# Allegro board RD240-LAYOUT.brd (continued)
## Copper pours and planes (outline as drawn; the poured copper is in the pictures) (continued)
CS on BOTTOM: 256.9,5.21 256.89,5.28 256.9,5.35 256.95,5.4 256.91,5.43 256.89,5.47 256.89,5.52 256.95,5.64 257.08,5.66 257.46,5.55 257.62,5.55 257.78,5.58 257.95,5.75 257.95,6.47 257.81,6.61 257.62,6.65 256.3,6.65 256.24,6.66 256.19,6.69 254.96,7.93 254.92,7.98 254.91,8.04 254.91,8.24 254.78,8.61 254.77,8.66 254.76,8.71 254.76,8.82 255.06,9.12 255.36,8.82 255.36,8.71 255.36,8.66 255.34,8.61 255.21,8.24 255.21,8.1 256.36,6.95 257.62,6.95 257.95,7.02 258,7.03 258.18,7.03 258.33,6.96 258.4,6.8 258.4,5.4 258.33,5.24 258.18,5.17 258,5.17 257.95,5.18 257.62,5.25 257.46,5.25 257.08,5.14 257.01,5.13 256.95,5.16
CS on BOTTOM: 262.17,6.39 261.79,6.5 261.43,6.5 261.37,6.51 261.32,6.54 261.21,6.65 261.2,6.65 259.58,6.65 259.25,6.58 259.2,6.58 259.02,6.58 258.8,6.8 259.02,7.03 260.65,7.03 260.97,7.09 261.02,7.1 261.2,7.1 261.36,7.03 261.42,6.86 261.49,6.8 261.79,6.8 262.17,6.91 262.23,6.92 262.28,6.9 262.35,6.83 262.36,6.73 262.34,6.69 262.3,6.65 262.32,6.64 262.34,6.61 262.36,6.58 262.34,6.44 262.21,6.38
CS on BOTTOM: 243.29,13.6 239.59,13.6 239.49,13.62 239.41,13.67 235.3,17.78 233.7,17.78 233.61,17.8 233.53,17.86 223.77,27.62 223.59,27.62 223.56,27.6 223.04,27.45 222.97,27.45 222.7,27.45 222.52,27.45 222.35,27.51 222.16,27.74 222.14,28.03 222.14,28.15 222.14,28.22 222.16,28.28 222.35,28.92 222.35,29.51 222.33,29.53 222.31,29.54 222.24,29.61 222.21,29.65 222.2,29.71 222.2,29.8 222.24,29.91 222.35,29.95 222.36,29.95 222.6,30.13 222.84,29.95 222.85,29.95 222.96,29.91 223,29.8 223,29.71 222.99,29.65 222.96,29.61 222.89,29.54 222.87,29.53 222.85,29.51 222.85,28.92 223.02,28.37 223.06,28.36 223.1,28.35 223.75,28.16 223.83,28.16 223.92,28.14 224,28.09 233.81,18.28 235.41,18.28 235.5,18.26 235.58,18.21 239.69,14.1 243.39,14.1 243.49,14.08 243.57,14.03 244.16,13.44 244.16,13.08 243.81,13.08
CSA on TOP (solid shape): 107.08,84.48 107.12,84.62 107.24,84.67 108.5,84.54 108.6,84.5 108.64,84.4 108.59,84.29 108.49,84.25 108.47,84.25 108.24,84.27 107.61,83.56 107.67,83.33 107.56,83.14 107.38,83.26
CSA on TOP: 130.48,48.24 130.31,48.3 130.33,48.49 130.35,48.5 130.33,48.51 130.31,48.7 130.48,48.76 130.84,48.65 134.76,48.65 135.45,49.34 135.36,49.63 135.35,49.67 135.35,49.71 135.35,49.9 135.43,50.09 135.62,50.17 136.22,50.17 136.26,50.17 136.31,50.16 136.66,50.05 137.18,50.05 137.24,50.04 137.29,50.01 137.53,49.76 137.8,49.82 137.88,49.83 138.1,49.6 137.88,49.38 137.8,49.38 137.41,49.47 137.38,49.49 137.12,49.75 136.66,49.75 136.31,49.64 136.26,49.63 136.22,49.62 135.89,49.62 135.77,49.26 135.75,49.22 135.73,49.19 134.93,48.39 134.89,48.37 134.86,48.35 134.82,48.35 130.84,48.35
CSA on BOTTOM: 157.43,1.52 157.2,1.75 157.43,1.98 157.55,1.98 157.6,1.97 157.93,1.9 158.74,1.9 159.05,2.21 159.05,2.86 158.94,3.22 159,3.39 159.19,3.37 159.2,3.35 159.21,3.37 159.4,3.39 159.46,3.22 159.35,2.86 159.35,2.15 159.34,2.09 158.91,1.64 158.87,1.62 158.83,1.6 158.8,1.6 157.93,1.6 157.6,1.53 157.55,1.52
CSA on BOTTOM: 156.4,1.52 156.35,1.53 156.02,1.6 154.93,1.6 154.87,1.61 154.82,1.64 154.58,1.88 154.23,2.14 154.2,2.25 154.2,2.41 154.21,2.46 154.26,2.7 152.86,4.1 152.3,4.1 152.26,4.11 152.22,4.13 152.2,4.14 151.89,4.42 151.24,5.08 150.43,5.08 150.22,5.28 150.43,5.47 150.96,5.47 151.28,5.42 151.32,5.41 151.36,5.38 152.1,4.64 152.36,4.4 152.93,4.4 152.98,4.39 153.03,4.36 154.53,2.86 154.56,2.82 154.57,2.78 154.64,2.46 154.65,2.41 154.65,2.32 154.8,2.09 154.99,1.9 156.02,1.9 156.35,1.97 156.4,1.98 156.57,1.98 156.8,1.75 156.57,1.52
CSB on TOP: 123.9,82.45 122.85,83.5 123.9,84.55 124.7,84.55 124.99,84.51 125.26,84.39 126.01,83.91 126.56,83.91 126.67,83.86 126.71,83.75 126.72,83.73 126.75,83.64 126.71,83.55 126.71,83.53 126.67,83.42 126.56,83.38 126.54,83.38 126.5,83.36 126.45,83.35 126.42,83.35 124.99,82.49 124.7,82.45
CSB on TOP: 152.16,44.85 152.1,44.85 152.04,44.86 151.99,44.89 151.77,45.12 151.74,45.17 151.72,45.23 151.72,45.56 151.67,45.73 151.43,45.73 151.39,45.73 151.35,45.74 150.96,45.85 150.82,45.85 150.77,45.86 150.72,45.89 150.59,46.02 150.45,46.02 150.13,45.96 150.08,45.95 149.9,45.95 149.68,46.17 149.9,46.4 150.08,46.4 150.13,46.39 150.45,46.33 150.65,46.33 150.71,46.31 150.89,46.15 150.96,46.15 151.35,46.26 151.39,46.27 151.43,46.27 151.88,46.27 152.1,46.16 152.14,45.92 152.03,45.56 152.03,45.29 152.16,45.15 152.16,45.15 152.52,45.26 152.69,45.2 152.67,45.01 152.65,45 152.67,44.99 152.69,44.8 152.52,44.74
CSB on BOTTOM: 156.4,2.92 156.35,2.93 156.02,3 154.9,3 154.84,3.01 154.79,3.04 153.51,4.33 153.48,4.36 153.4,4.74 153.06,4.81 152.43,4.82 152.38,4.85 151.51,5.72 150.43,5.72 150.22,5.92 150.43,6.12 151.12,6.12 151.15,6.12 151.43,6.08 151.53,6.08 151.58,6.06 152.55,5.11 153.06,5.11 153.39,5.18 153.44,5.18 153.62,5.18 153.77,5.12 153.84,4.96 153.84,4.79 153.83,4.75 153.78,4.48 154.96,3.3 156.02,3.3 156.35,3.37 156.4,3.38 156.57,3.38 156.8,3.15 156.57,2.92
CSB on BOTTOM: 126.41,83.46 126.36,83.52 126.19,83.85 126.09,83.94 126.06,83.99 126.05,84.05 126.05,85.3 126.06,85.36 126.49,85.81 126.53,85.83 127.06,86.1 127.26,86.04 127.21,85.84 127.2,85.83 126.97,85.72 126.97,85.68 127.2,85.57 127.21,85.56 127.26,85.36 127.06,85.3 126.72,85.47 126.58,85.47 126.35,85.24 126.35,84.11 126.4,84.06 126.73,83.89 126.76,83.87 126.78,83.84 126.8,83.71 126.69,83.62 126.67,83.61 126.64,83.61 126.64,83.58 126.63,83.55 126.58,83.47 126.49,83.44
FG1 on BOTTOM: 27.31,41.8 27.25,41.81 27.21,41.84 23.94,45.1 23.91,45.15 23.9,45.21 23.9,48.19 23.9,48.21 23.92,48.22 24.73,49.02 25.39,49.95 25.4,49.96 33.94,58.51 33.99,58.54 34.05,58.55 40.49,58.55 40.55,58.54 40.59,58.51 42.86,56.24 42.89,56.2 42.9,56.14 42.9,52.03 42.89,51.98 42.86,51.93 32.77,41.84 32.72,41.81 32.66,41.8
FG2 on BOTTOM: 6.11,0.62 5.82,0.68 5.58,0.84 4.72,1.7 4.56,1.94 4.5,2.23 4.5,6.75 4.72,7.28 5.25,7.5 9.35,7.5 9.64,7.44 9.88,7.28 10.62,6.54 13.8,4.75 20.83,4.75 21.31,5.23 22.37,5.23 22.37,4.17 21.68,3.47 21.43,3.31 21.14,3.25 13.8,3.25 11.12,1.74 10.22,0.84 9.98,0.68 9.69,0.62
FG3 on BOTTOM: 68.04,52.19 67.2,52.19 67.14,52.13 67.07,52.07 65.01,50.63 64.99,50.62 63.96,50.82 64.15,51.86 65.75,52.98 65.75,54.02 64.15,55.14 64.01,55.26 63.91,55.42 63.72,55.4 63.54,55.43 61.6,55.97 60.53,54.9 61.07,52.96 60.57,52.04 59.64,52.52 59.63,52.56 58.37,57.07 57.6,57.92 57.54,58.21 57.54,58.55 58.29,59.3 59.04,58.55 59.04,58.52 59.43,58.13 63.94,56.87 63.98,56.86 64.23,56.72 64.41,56.49 64.71,56.49 64.99,56.38 65.01,56.37 68.23,54.11 68.28,54.07 68.33,54.03 71.63,50.73 71.63,49.67 70.57,49.67
FG4 on BOTTOM (solid shape): 78.41,10.05 79.3,10.6 80.19,10.05 82.43,5.56 82.39,4.59 81.54,4.12 81.01,4.27 80.64,4.67 80.36,5.24 78.24,5.24 77.96,4.67 76.62,4.22 76.17,5.56
FG4 on BOTTOM: 75.95,0.5 75.84,0.54 75.8,0.65 75.8,3.85 75.84,3.96 75.95,4 76.65,4 76.76,3.96 76.8,3.86 77.36,2.42 78.65,1.59 78.92,1.89 79.31,2 80.81,2.01 81.07,2.23 81.29,2.49 81.29,2.73 81.29,2.73 81.25,2.97 81.29,3.21 81.29,3.22 81.3,3.99 82.05,4.73 82.8,3.98 82.8,3.87 82.8,3.85 82.8,3.23 84.01,2.02 110.05,2.02 111.99,3.96 113.05,3.96 113.05,2.9 110.89,0.74 110.65,0.58 110.36,0.52 83.07,0.52 83.04,0.51 83,0.5
FG6 on BOTTOM: 295,12.65 295.04,12.76 295.15,12.8 295.59,12.8 295.65,12.79 295.69,12.76 296.15,12.3 299,12.3 299.4,12.7 299.4,16.45 299.4,16.48 299.41,16.5 299.4,16.52 299.4,16.55 299.4,18.65 299.41,18.7 299.44,18.75 304.39,23.7 304.51,23.88 304.55,24.09 304.55,39.76 304.53,39.91 304.46,40.08 304.45,40.12 304.45,43.35 304.49,43.46 304.6,43.5 305.7,43.5 305.91,43.41 306,43.2 306,16.55 306,16.52 305.99,16.5 306,16.48 306,16.45 306,2 305.56,0.94 304.5,0.5 295.87,0.5 295.76,0.52 295.66,0.59 295.09,1.16 295.02,1.26 295,1.37 295,4.5 ; 2 cut-outs
FG7 on BOTTOM: 296.2,127.58 296.24,127.68 296.35,127.72 297,127.72 297.15,127.88 297.2,127.91 297.26,127.92 298.52,127.92 298.67,127.96 298.73,128.01 298.87,128.15 298.95,128.29 298.96,128.36 298.96,130.42 298.97,130.48 299,130.52 300.89,132.41 300.95,132.46 301.1,132.5 302.48,132.5 302.52,132.5 304.5,132.5 305.09,132.38 305.56,132.06 305.89,131.56 306,131 306,127.88 305.99,127.81 305.91,127.67 305.58,127.34 302.73,125.51 299.66,126.96 296.35,126.96 296.24,127 296.2,127.11 ; 1 cut-out
GDA on TOP: 148.44,42.72 148.46,42.75 148.52,42.87 144.04,47.35 142.1,47.35 142.04,47.36 141.99,47.39 141.67,47.72 141.64,47.77 141.62,47.83 141.62,47.87 141.56,48.17 141.55,48.23 141.55,48.56 141.56,48.61 141.64,48.97 141.79,49.13 141.79,50.14 142.06,50.42 142.34,50.14 142.34,49.52 142.33,49.46 142.14,49.07 142.13,49.04 142.11,49.02 142,48.91 142,48.58 142,48.56 142,48.23 141.99,48.17 141.93,47.88 142.16,47.65 144.1,47.65 144.16,47.64 148.81,43.01 148.83,42.97 148.94,42.75 148.96,42.72 148.96,42.68 148.9,42.56 148.76,42.54 148.73,42.56 148.7,42.58 148.67,42.56 148.64,42.54 148.5,42.56 148.44,42.68
GDB on TOP (solid shape): 139.58,2.27 139.54,2.47 139.75,2.51 140.81,1.77 140.87,1.65 140.81,1.53 139.75,0.79 139.59,0.78 139.51,0.91 139.53,0.98 139.58,1.03 139.78,1.17 139.78,2.13
GDB on TOP: 149.76,42.33 149.58,42.31 149.51,42.49 149.6,42.69 144.69,47.62 144.68,47.67 144.68,47.87 144.61,48.17 144.6,48.23 144.6,48.98 144.53,49.1 144.4,49.3 144.35,49.41 144.33,49.53 144.33,50.14 144.74,50.55 145.16,50.14 145.16,49.53 145.15,49.46 145.14,49.4 144.98,48.91 145.04,48.63 145.05,48.58 145.05,48.23 145.04,48.17 144.97,47.87 144.97,47.74 149.88,42.83 149.91,42.78 150.03,42.49 149.97,42.31 149.78,42.33 149.77,42.34
HS1_1 on TOP: 175.2,122.9 175.14,122.91 175.09,122.93 175.05,122.95 175.02,122.97 173.43,124.57 171.34,126.32 171.3,126.37 171.28,126.42 171.36,126.72 171.67,126.71 172.75,125.79 174.45,125.79 175.53,126.71 175.57,126.73 175.62,126.75 175.88,126.68 175.93,126.42 175.9,126.37 175.85,126.32 174.18,124.91 174.13,124.86 174.13,124.58 175.3,123.4 176.57,123.4 176.82,123.15 176.57,122.9
HS1_2 on TOP (solid shape): 88.47,131.85 88.73,131.87 88.86,131.65 88.84,131.53 88.76,131.44 87.94,130.86 87.94,127.14 88.76,126.56 88.82,126.21 88.47,126.15 84.75,128.8 84.65,129 84.75,129.2 87.54,131.19
LGND on TOP (solid shape): 221.06,23.49 221.23,23.21 221.53,22 221.32,21.47 220.75,21.48 220.18,21.47 219.97,22 220.26,23.21 220.44,23.49 220.75,23.6
LGND on TOP: outline of 128 points within 226.85,55.94 242.53,90.55 ; 2 cut-outs
LGND on TOP: 231.3,16.58 230.94,16.94 231.3,17.3 231.32,17.3 231.39,17.29 231.46,17.28 231.73,17.17 232.02,17.17 232.4,17.28 232.44,17.29 232.48,17.29 233.69,17.29 233.73,17.29 234.15,17.17 234.74,17.17 235.13,17.28 235.17,17.29 235.22,17.28 235.29,17.23 235.32,17.14 235.32,17.12 235.34,17.07 235.35,17.02 235.34,16.97 235.32,16.92 235.32,16.9 235.26,16.78 235.13,16.75 234.74,16.87 234.15,16.87 233.73,16.75 233.69,16.74 232.48,16.74 232.44,16.75 232.4,16.75 232.28,16.79 231.93,16.79 231.46,16.6 231.39,16.59 231.32,16.58
LGND on TOP: outline of 210 points within 232.9,48 306,132.5
LGND on TOP: 214.52,15.45 214.43,15.88 214.45,15.94 214.48,16 214.45,16.06 214.43,16.12 214.52,16.55 214.92,16.74 214.98,16.74 215.04,16.72 215.7,16.55 219.44,20.3 219.44,20.52 219.27,20.69 219.16,20.86 219.12,21.05 219.12,21.26 219.16,21.45 219.27,21.61 219.45,21.8 219.62,21.91 219.81,21.95 220.62,21.95 221.05,21.86 221.25,21.46 221.25,20.9 221.21,20.71 221.1,20.55 216.2,15.65 216.1,15.57 215.97,15.52 215.04,15.27 214.98,15.26 214.92,15.26
LGND on BOTTOM: outline of 92 points within 225.45,76 242.45,93.3
LGND on BOTTOM: outline of 129 points within 232.9,48.23 305,132.5 ; 6 cut-outs
LGND on BOTTOM: 234.86,109.05 234.8,109.06 234.76,109.09 234.05,109.8 233.05,109.8 232.94,109.84 232.9,109.95 232.9,112.99 232.97,113.12 233.11,113.13 233.15,113.11 233.96,113.34 233.67,114.13 233.65,114.14 233.4,114.22 233.14,114.19 232.96,114.24 232.98,114.43 233.61,115.06 233.65,115.09 233.71,115.1 235.02,115.1 235.05,115.17 235.05,115.42 235.07,115.52 235.12,115.6 235.5,115.98 235.85,115.98 235.85,115.62 235.55,115.32 235.55,115.17 235.58,115.1 237.4,115.1 239.06,116.76 239.1,116.79 239.16,116.8 240.45,116.8 240.56,116.76 240.6,116.65 240.6,109.2 240.56,109.09 240.45,109.05
LGND on BOTTOM: 289.82,42.61 289.9,42.6 292.76,42.6 292.94,42.63 293.08,42.73 293.86,43.51 293.9,43.54 293.96,43.55 300.3,43.55 300.42,43.53 302.68,41.3 304.11,39.87 304.14,39.82 304.15,39.76 304.15,24.09 304.14,24.03 304.11,23.98 298.99,18.86 298.91,18.73 298.9,18.65 298.9,13.94 298.89,13.88 298.86,13.83 298.78,13.75 298.62,13.48 298.6,13.33 298.6,12.9 298.56,12.79 298.45,12.75 296.26,12.75 296.2,12.76 296.16,12.79 295.84,13.11 295.7,13.19 295.63,13.2 282.72,13.2 282.65,13.21 282.51,13.29 280.95,14.85 274.58,14.85 274.52,14.86 274.48,14.89 273.84,15.53 273.81,15.57 273.8,15.63 273.8,43.25 273.84,43.4 273.95,43.51 274.1,43.55 288.9,43.55 289.05,43.51 289.16,43.4 289.2,43.25 289.2,43.07 289.24,42.92 289.29,42.86 289.37,42.78 289.38,42.77 289.51,42.66 289.67,42.62 ; 3 cut-outs
LGND on BOTTOM: 234.48,55.97 234.39,56 234.33,56.08 234.26,56.22 234.08,56.35 234.05,56.4 234.02,56.43 233.1,56.43 232.99,56.47 232.95,56.58 232.95,60 232.96,60.06 232.99,60.1 233.15,60.26 233.19,60.29 233.25,60.3 235.93,60.3 235.96,60.3 236,60.28 236.65,60.39 236.77,61.05 236.76,61.14 236.8,61.22 236.87,61.34 236.9,61.48 236.9,62.12 236.79,62.39 236.53,62.5 234.36,62.5 234.3,62.51 234.26,62.54 234.25,62.55 234.21,62.6 234.2,62.66 234.07,62.79 233.1,62.79 232.99,62.83 232.95,62.94 232.95,65.73 232.99,65.84 233.1,65.88 233.31,65.88 233.49,66.06 233.49,66.38 233.5,66.42 233.52,66.67 233.43,66.91 233.41,67.01 233.45,67.1 235.91,69.56 235.97,69.61 236.12,69.65 239.16,69.65 239.2,69.64 239.35,69.57 239.47,69.55 240.24,69.55 240.35,69.57 240.5,69.64 240.54,69.65 241.3,69.65 241.45,69.61 241.56,69.5 241.6,69.35 241.6,58.75 241.59,58.69 241.56,58.65 238.92,56.01 238.88,55.98 238.82,55.97
LGND on BOTTOM: 222.19,24.75 222.13,24.76 222.06,24.77 221.42,24.96 220.27,24.96 220.17,24.98 220.09,25.03 219.87,25.25 219.87,25.61 220.22,25.61 220.37,25.46 221.42,25.46 222.06,25.65 222.13,25.67 222.19,25.67 222.58,25.67 223.04,25.21 222.58,24.75
LGND on BOTTOM: 239.26,119.28 239.2,119.29 239.16,119.32 238.92,119.56 238.89,119.6 238.88,119.66 238.88,121.3 238.71,121.71 238.3,121.88 235.17,121.88 235.06,121.92 235.02,122.03 235.02,123.15 235.06,123.26 235.17,123.3 239.85,123.3 239.91,123.29 239.95,123.26 240.16,123.05 240.19,123.01 240.2,122.95 240.2,119.46 240.19,119.4 240.16,119.36 240.12,119.32 240.07,119.29 240.01,119.28
LGND on CONDUCTIVE2: outline of 167 points within 194.56,1.55 304.95,131.45 ; 167 cut-outs
LGND on CONDUCTIVE5: outline of 187 points within 194.56,1.55 304.95,131.45 ; 166 cut-outs
OUTA1 on TOP: 140.68,115.44 140.51,115.5 140.53,115.69 140.55,115.7 140.53,115.71 140.51,115.9 140.68,115.96 141.04,115.85 142.15,115.85 142.47,116.18 142.47,116.42 142.41,116.75 142.4,116.8 142.4,116.94 142.41,116.98 142.49,117.37 142.67,117.55 142.67,117.65 142.5,118.07 142.54,118.4 142.84,118.56 143.06,118.56 143.13,118.55 143.2,118.53 143.63,118.35 144.29,118.35 144.59,118.65 144.63,118.68 144.67,118.69 144.7,118.7 145.07,118.7 145.54,118.92 145.63,118.95 145.72,118.96 146.45,118.96 146.86,118.55 146.45,118.14 145.72,118.14 145.63,118.15 145.54,118.17 145.07,118.4 144.76,118.4 144.46,118.09 144.42,118.07 144.39,118.05 144.35,118.05 143.63,118.05 143.14,117.85 143.09,117.84 142.99,117.6 142.99,117.51 142.98,117.45 142.8,117.26 142.8,117.2 142.84,116.98 142.85,116.94 142.85,116.8 142.84,116.75 142.78,116.42 142.78,116.11 142.76,116.06 142.32,115.59 142.28,115.57 142.24,115.55 142.21,115.55 141.04,115.55
OUTB1 on TOP: 140.68,112.04 140.51,112.1 140.53,112.29 140.55,112.3 140.53,112.31 140.51,112.5 140.68,112.56 141.04,112.45 142.16,112.45 142.47,112.77 142.47,113.02 142.41,113.35 142.4,113.4 142.4,113.55 142.41,113.6 142.49,113.98 142.65,114.15 142.65,114.29 142.5,114.67 142.54,115 142.84,115.16 143.06,115.16 143.13,115.15 143.41,115.04 143.63,115.04 143.75,115.16 143.75,115.9 143.76,115.96 145.03,117.25 145.08,117.28 145.14,117.29 145.32,117.29 145.67,117.4 145.71,117.41 145.75,117.42 146.45,117.42 146.72,117.14 146.45,116.86 145.75,116.86 145.71,116.87 145.67,116.88 145.32,116.99 145.2,116.99 144.05,115.84 144.05,115.1 144.04,115.04 143.68,114.68 143.66,114.66 143.14,114.45 143.09,114.44 142.99,114.2 142.99,114.12 142.98,114.07 142.95,114.02 142.81,113.88 142.81,113.78 142.84,113.6 142.85,113.55 142.85,113.4 142.84,113.35 142.78,113.02 142.78,112.7 142.76,112.65 142.33,112.19 142.29,112.17 142.25,112.15 142.22,112.15 141.04,112.15
OUTC1 on TOP: 151.9,67.95 150.85,69 151.9,70.05 152.67,70.05 153.62,70.1 153.68,70.17 153.72,70.19 153.76,70.21 153.79,70.21 154.13,70.21 154.56,70.39 154.9,70.36 155.06,70.06 155.06,69.84 155.05,69.77 155.03,69.7 154.85,69.27 154.85,69.14 155.4,68.59 155.59,68.63 155.67,68.99 156,69.33 156,69.77 155.78,70.24 155.75,70.33 155.74,70.42 155.74,71.15 156.15,71.56 156.56,71.15 156.56,70.42 156.55,70.33 156.53,70.24 156.3,69.77 156.3,69.27 156.29,69.21 155.96,68.87 156.02,68.6 156.03,68.56 156.03,68.42 155.96,68.27 155.8,68.2 155.72,68.2 155.67,68.21 155.28,68.29 155.25,68.32 154.59,68.97 154.56,69.02 154.55,69.08 154.55,69.27 154.35,69.76 154.34,69.82 154.13,69.91 153.85,69.91 153.83,69.89 153.75,68.91 153.41,68.23 152.7,67.95
OUTD1 on TOP: 157.2,68.2 157.04,68.27 156.97,68.42 156.97,68.6 156.98,68.65 157.05,68.98 157.05,69.33 157.06,69.38 157.09,69.43 157.41,69.75 157.41,70.04 157.3,70.39 157.29,70.43 157.28,70.47 157.28,71.15 157.56,71.42 157.84,71.15 157.84,70.47 157.83,70.43 157.82,70.39 157.71,70.04 157.7,69.63 157.67,69.58 157.35,69.26 157.35,68.98 157.38,68.85 157.38,68.76 157.52,68.62 157.71,68.62 158.29,69.21 158.34,69.24 158.4,69.25 160.31,69.25 160.7,69.36 160.76,69.37 160.82,69.34 160.87,69.29 160.89,69.22 160.87,69.15 160.83,69.1 160.87,69.05 160.89,68.98 160.83,68.86 160.7,68.84 160.31,68.95 158.46,68.95 157.83,68.32 157.8,68.29 157.76,68.28 157.41,68.21 157.37,68.2
OUTD1 on TOP: 147.6,71.45 146.55,72.5 147.6,73.55 148.85,73.55 149.17,73.5 149.45,73.36 150.47,72.65 150.89,72.65 151.75,73.51 151.75,75.25 151.76,75.31 152.39,75.95 152.56,76.28 152.58,76.31 152.61,76.33 152.74,76.35 152.83,76.24 152.84,76.22 152.84,76.19 152.86,76.19 153,76.07 152.93,75.91 152.6,75.74 152.05,75.19 152.05,73.45 152.04,73.39 151.06,72.39 151.02,72.37 150.98,72.35 150.95,72.35 150.47,72.35 149.45,71.64 149.17,71.5 148.85,71.45
OUTF on TOP: 234.05,104.34 234.05,105.8 234.06,105.86 235.04,106.85 235.08,106.88 235.11,106.89 235.14,106.89 235.5,106.89 235.98,107.12 236.06,107.14 236.16,107.16 236.66,107.16 237.07,106.74 236.66,106.33 236.16,106.33 236.06,106.34 235.98,106.37 235.5,106.59 235.2,106.59 234.35,105.74 234.35,104.34 234.46,103.98 234.4,103.81 234.21,103.83 234.2,103.85 234.19,103.83 234,103.81 233.94,103.98
PN on TOP (solid shape): 190.61,7.74 190.76,7.39 190.74,7.26 190.69,7.14 190.03,5.95 189.45,5.71 189.09,6.22 188.58,6.58 188.82,7.16 190.01,7.82 190.13,7.87 190.26,7.89
PN on BOTTOM (solid shape): 126.98,27.15 127.14,27.28 127.28,27.13 127.28,27.11 127.18,26.4 129.1,24.48 129.81,24.58 129.98,24.45 129.85,24.28 126.72,23.85 126.59,23.89 126.55,24.02
PN on BOTTOM (solid shape): 84.13,70.67 84.28,70.32 84.26,70.17 84.2,70.04 83.56,69.06 83.07,68.84 82.66,69.2 82.3,69.6 82.52,70.1 83.64,70.8 83.78,70.82
PN on BOTTOM (solid shape): 177.57,2.62 178.15,2.86 179.48,2.48 179.84,2 179.48,1.52 178.15,1.14 177.57,1.38 177.69,2
PN on CONDUCTIVE2 (solid shape): 84.13,70.67 84.28,70.32 84.26,70.17 84.2,70.04 83.56,69.06 83.07,68.84 82.66,69.2 82.3,69.6 82.52,70.1 83.64,70.8 83.78,70.82
PN on CONDUCTIVE5 (solid shape): 84.13,70.67 84.28,70.32 84.26,70.17 84.2,70.04 83.56,69.06 83.07,68.84 82.66,69.2 82.3,69.6 82.52,70.1 83.64,70.8 83.78,70.82
PN on TOP: 177.4,3.51 177.4,4.31 177.44,4.5 177.55,4.66 179.25,6.36 179.41,6.47 179.6,6.51 180.45,6.51 180.75,6.81 180.92,6.92 181.11,6.96 181.99,6.96 182.18,6.92 182.35,6.81 182.65,6.51 184.9,6.51 185.29,6.84 185.48,6.88 187.76,6.88 189.01,7.24 189.57,7.01 189.5,6.4 189.48,6.38 189.5,6.36 189.57,5.75 189.01,5.52 187.76,5.88 185.69,5.88 185.46,5.65 185.3,5.55 185.11,5.51 182.65,5.51 182.25,5.1 182.08,5 181.89,4.96 181.21,4.96 181.02,5 180.85,5.1 180.45,5.51 179.81,5.51 178.4,4.1 178.4,3.51 178.76,2.25 178.54,1.68 177.93,1.76 177.9,1.79 177.87,1.76 177.26,1.68 177.04,2.25
PN on TOP: 143.08,104.5 142.92,104.56 142.84,104.71 142.12,106.38 140.74,107.55 140.64,107.65 140.6,107.78 140.6,110.55 140.67,110.73 140.85,110.8 144.6,110.8 144.78,110.98 144.78,115.6 144.8,115.7 144.85,115.78 145.12,116.05 145.2,116.1 145.3,116.12 146.45,116.12 146.7,115.87 146.45,115.62 145.4,115.62 145.28,115.5 145.28,113.67 145.37,113.58 146.45,113.58 146.7,113.33 146.45,113.08 145.37,113.08 145.28,112.99 145.28,109.92 145.5,109.7 145.65,109.7 145.83,109.63 145.9,109.45 145.9,109.35 145.83,109.17 145.65,109.1 144.8,109.1 144.3,108.6 144.3,104.75 144.23,104.57 144.05,104.5
PN on TOP: 164.1,68.1 163.99,68.14 163.95,68.25 163.91,68.46 163.77,68.69 163.76,68.74 163.76,69.59 163.8,69.7 163.91,69.75 164.9,69.75 164.97,69.77 165,69.84 165,70.15 165.04,70.26 165.15,70.3 165.54,70.3 165.6,70.29 165.64,70.26 165.75,70.15 166.3,70.15 166.45,70.11 166.56,70 166.6,69.85 166.6,69.3 166.64,69.15 166.75,69.04 166.9,69 170.35,69 170.5,68.96 170.61,68.85 170.65,68.7 170.65,68.4 170.61,68.25 170.5,68.14 170.35,68.1
PN on TOP: 173.95,14.82 173.72,14.98 173.77,15.25 173.78,15.25 174.9,16.38 174.9,18.24 174.91,18.3 174.94,18.34 175.08,18.48 175.13,18.52 175.23,18.54 175.26,18.54 177.27,18.54 177.33,18.53 177.38,18.49 177.41,18.45 177.42,18.39 177.42,15.4 177.38,15.29 177.27,15.25 175.58,15.25 175.2,14.87 175.16,14.85 175.11,14.83
PN on TOP: 165.25,129.39 165.19,129.4 165.15,129.43 164.93,129.65 164.9,129.69 164.89,129.75 164.89,132.17 164.9,132.23 164.93,132.27 165.21,132.55 165.25,132.58 165.31,132.59 167.29,132.59 167.35,132.58 167.39,132.55 167.65,132.29 167.68,132.25 167.69,132.19 167.69,129.69 167.68,129.63 167.65,129.59 167.49,129.43 167.45,129.4 167.39,129.39
PN on TOP: 142.62,48.17 142.4,48.4 142.62,48.62 143.01,48.62 143.11,48.73 143.11,48.95 143.06,49.34 143.06,49.37 143.06,50.99 143.06,51.02 143.11,51.43 143.13,51.5 143.18,51.56 143.58,51.96 143.65,52.01 143.74,52.02 144.27,52.02 144.67,52.07 144.69,52.07 144.87,51.99 144.91,51.8 144.87,51.61 144.69,51.53 144.67,51.53 144.27,51.58 143.83,51.58 143.57,51.32 143.61,51.02 143.61,50.99 143.61,49.37 143.61,49.34 143.56,48.95 143.56,48.73 143.66,48.62 143.97,48.62 144.2,48.4 143.97,48.17
PN on TOP: 164.05,80.97 163.86,81.06 163.78,81.25 163.78,81.94 163.78,81.98 163.79,82.02 163.89,82.35 163.19,83.05 161.25,83.05 161.19,83.06 161.14,83.09 159.79,84.44 159.76,84.49 159.75,84.55 159.75,85.07 158.63,86.54 158.61,86.59 158.6,86.74 158.57,86.77 158.54,86.81 158.53,86.87 158.53,89.02 158.54,89.08 158.57,89.12 158.85,89.4 158.89,89.43 158.95,89.44 160.93,89.44 160.99,89.43 161.03,89.4 161.29,89.14 161.32,89.1 161.33,89.04 161.33,86.82 161.32,86.76 161.29,86.72 161.2,86.63 161.19,86.58 161.17,86.54 160.05,85.07 160.05,84.61 161.31,83.35 163.25,83.35 163.31,83.34 164.19,82.46 164.2,82.4 164.2,82.37 164.31,82.02 164.32,81.98 164.32,81.94 164.32,81.51 164.71,81.4 170.66,81.4 170.8,81.54 170.99,81.82 171.01,81.85 171.13,81.89 171.24,81.82 171.26,81.78 171.28,81.77 171.36,81.68 171.34,81.55 171.32,81.53 171.3,81.51 171.02,81.33 170.83,81.14 170.79,81.12 170.76,81.1 170.72,81.1 164.71,81.1 164.33,80.99 164.29,80.98 164.25,80.97
PN on TOP: 161.67,68.95 161.55,69.1 161.55,69.43 161.31,69.67 159.12,69.67 159.07,69.69 159.02,69.72 158.72,70.01 158.7,70.04 158.69,70.07 158.56,70.48 158.56,70.52 158.56,71.15 158.83,71.42 159.1,71.15 159.1,70.06 159.19,69.97 161.03,69.97 161.09,70.04 161.09,71.15 161.37,71.42 161.65,71.15 161.65,70.52 161.64,70.48 161.63,70.44 161.52,70.08 161.52,69.89 161.81,69.6 161.83,69.58 162.06,69.25 162.08,69.15 162.03,69.07 161.98,69.03 161.93,69.02 161.88,69.03 161.84,69.05
PN on TOP: 82.9,68.96 83.03,69.24 83.43,69.42 83.43,69.52 83.03,69.7 82.9,69.98 83.14,70.17 83.19,70.17 83.24,70.15 84.1,69.76 87.25,72.9 87.25,73.2 87.22,73.23 87.17,73.31 87.15,73.4 87.15,73.6 87.17,73.69 87.22,73.77 87.25,73.8 87.25,74.42 87.27,74.52 87.32,74.6 88.15,75.43 88.5,75.43 88.5,75.07 87.75,74.32 87.75,73.8 87.78,73.77 87.83,73.69 87.85,73.6 87.85,73.4 87.83,73.31 87.78,73.23 87.75,73.2 87.75,72.8 87.73,72.7 87.68,72.62 84.34,69.29 84.27,69.24 84.19,69.22 83.24,68.79 83.19,68.77 83.14,68.76
PN on TOP: 154.41,71.13 154.39,71.16 154.14,71.58 152.88,72.84 152.83,72.91 152.81,73 152.81,74.99 152.83,75.08 152.88,75.15 153.04,75.31 153.28,75.62 153.3,75.64 153.46,75.71 153.62,75.64 153.65,75.6 153.69,75.57 153.76,75.41 153.69,75.25 153.67,75.23 153.36,74.99 153.26,74.9 153.26,73.09 154.46,71.9 154.88,71.65 154.91,71.63 154.93,71.62 154.99,71.48 154.96,71.33 154.89,71.27 154.81,71.23 154.77,71.15 154.71,71.08 154.56,71.05 154.42,71.11
PN on TOP, BOTTOM: 142.06,60.89 142,60.9 141.96,60.93 141.47,61.42 141.44,61.46 141.43,61.52 141.43,63.67 141.44,63.73 141.47,63.77 141.75,64.05 141.79,64.08 141.85,64.09 143.83,64.09 143.89,64.08 143.93,64.05 144.19,63.79 144.22,63.75 144.23,63.69 144.23,61.47 144.22,61.41 144.19,61.37 143.75,60.93 143.71,60.9 143.65,60.89
PN on TOP, BOTTOM: 110.86,60.89 110.8,60.9 110.76,60.93 110.27,61.42 110.24,61.46 110.23,61.52 110.23,63.67 110.24,63.73 110.27,63.77 110.55,64.05 110.59,64.08 110.65,64.09 112.63,64.09 112.69,64.08 112.73,64.05 112.99,63.79 113.02,63.75 113.03,63.69 113.03,61.47 113.02,61.41 112.99,61.37 112.55,60.93 112.51,60.9 112.45,60.89
PN on BOTTOM: 126.41,81.69 126.45,81.9 126.45,81.94 126.34,82.3 126.19,82.6 125.49,83.29 125.46,83.34 125.45,83.4 125.45,85.24 125.2,85.48 125.04,85.48 124.77,85.32 124.76,85.31 124.56,85.37 124.62,85.57 124.82,85.7 124.62,85.83 124.56,86.03 124.76,86.09 124.77,86.08 125.14,85.85 125.2,85.85 125.26,85.84 125.74,85.36 125.75,85.3 125.75,83.46 126.4,82.81 126.73,82.64 126.76,82.62 126.78,82.59 126.8,82.54 126.81,82.49 126.86,82.41 126.86,82.32 126.78,82.02 126.78,82.02 126.84,81.69 126.85,81.6 126.62,81.38 126.4,81.6
PN on BOTTOM: 151.34,1.57 151.3,1.7 151.38,2.03 151.38,2.08 151.39,2.14 151.54,2.31 151.54,2.41 151.39,2.81 151.38,2.88 151.38,3.05 151.49,3.3 151.74,3.41 151.92,3.41 152.35,3.5 152.72,3.61 152.76,3.62 152.83,3.6 152.88,3.56 152.94,3.55 152.99,3.53 153.02,3.51 153.04,3.48 153.21,3.15 153.71,2.65 153.79,2.3 153.78,2.19 153.68,2.12 153.64,2.12 153.6,2.12 153.57,2.14 153.5,2.12 153.43,2.14 153.38,2.18 153.36,2.23 153.35,2.27 153.35,2.59 153,2.94 152.69,3.1 152.58,3.13 152.45,3.13 152.39,3.07 152.26,2.86 152.18,2.76 152.06,2.71 151.88,2.25 151.87,2.22 151.85,2.19 151.69,2.03 151.69,1.97 151.75,1.7 151.71,1.57 151.6,1.52 151.53,1.53 151.45,1.52
PN on BOTTOM: 168.8,126.05 168.3,126.55 165.99,126.55 160.05,126.55 160,126.55 159.1,126.55 158.85,126.3 158.85,125.92 158.6,125.67 158.35,125.92 158.35,126.4 158.37,126.5 158.82,126.98 158.9,127.03 159,127.05 160,127.05 160.05,127.05 165.89,127.05 166.13,127.29 166.13,129.05 165.79,129.39 165.25,129.39 165.19,129.4 165.15,129.43 164.93,129.65 164.9,129.69 164.89,129.75 164.89,132.17 164.9,132.23 164.93,132.27 165.21,132.55 165.25,132.58 165.31,132.59 167.29,132.59 167.35,132.58 167.39,132.55 167.65,132.29 167.68,132.25 167.69,132.19 167.69,129.67 167.68,129.61 167.65,129.57 167.51,129.43 167.47,129.4 167.41,129.39 166.77,129.39 166.43,129.05 166.43,127.29 166.67,127.05 168.4,127.05 168.5,127.03 169.23,126.33 169.28,126.25 169.3,126.15 169.3,124.65 169.05,124.4 168.8,124.65
PN on BOTTOM: 159.16,86.24 159.1,86.25 159.06,86.28 158.57,86.77 158.54,86.81 158.53,86.87 158.53,89.02 158.54,89.08 158.57,89.12 158.85,89.4 158.89,89.43 158.95,89.44 160.93,89.44 160.99,89.43 161.03,89.4 161.29,89.14 161.32,89.1 161.33,89.04 161.33,86.82 161.32,86.76 161.29,86.72 160.85,86.28 160.81,86.25 160.75,86.24
PN on BOTTOM: 180.14,126.01 180.14,128.29 179.75,129.18 179.74,129.2 179.89,129.52 180.21,129.38 180.37,129.02 180.41,129.02 180.57,129.38 180.89,129.52 181.04,129.2 181.03,129.18 180.64,128.29 180.64,125.91 180.62,125.81 180.57,125.73 178.61,123.77 178.26,123.77 178.26,124.13
PN on BOTTOM: 151.55,10.29 151.55,10.75 151.56,10.81 152.72,11.98 152.76,12.01 152.79,12.02 152.82,12.03 153.05,12.03 153.35,12.09 153.4,12.1 153.58,12.1 153.63,12.09 153.95,12.03 154.18,12.03 154.78,12.62 154.78,12.65 154.71,12.97 154.7,13.02 154.7,13.2 154.93,13.43 155.15,13.2 155.15,13.02 155.14,12.97 155.07,12.65 155.07,12.55 155.06,12.5 154.35,11.77 154.31,11.74 154.28,11.73 154.25,11.72 153.95,11.72 153.63,11.66 153.58,11.65 153.4,11.65 153.35,11.66 153.05,11.72 152.89,11.72 151.85,10.69 151.85,10.29 151.96,9.93 151.9,9.76 151.71,9.78 151.7,9.8 151.69,9.78 151.5,9.76 151.44,9.93
PN on BOTTOM: 155.56,3.79 155.47,3.86 155.46,3.87 155.27,4.22 154.7,4.79 154.53,4.74 154.41,4.76 154.34,4.85 154.34,4.89 154.34,4.93 154.35,4.96 154.34,4.99 154.34,5.03 154.34,5.07 154.41,5.16 154.53,5.18 154.78,5.1 155.48,4.43 155.63,4.35 155.77,4.35 155.92,4.43 156.22,4.73 156.22,5 156.15,5.32 156.14,5.37 156.14,8.94 156.37,9.16 156.59,8.94 156.59,7.23 156.7,7.13 156.72,7.1 156.97,7.1 157.19,7.32 157.19,8.59 157.42,8.81 157.65,8.59 157.65,7.32 158.08,6.88 158.53,6.88 158.75,6.66 158.53,6.43 156.94,6.43 156.59,6.08 156.59,5.37 156.58,5.32 156.51,5 156.51,4.67 156.5,4.61 156.13,4.22 155.94,3.87 155.93,3.86 155.84,3.79 155.73,3.82 155.7,3.84 155.67,3.82
PN on BOTTOM: 142.5,7.25 142.28,7.47 142.5,7.7 143.01,7.7 143.13,7.82 143.13,7.93 142.86,8.2 142.38,8.2 142.33,8.21 141.94,8.29 141.91,8.32 141.8,8.43 141.72,8.43 141.58,8.29 141.53,8.26 141.48,8.25 140.5,8.25 140.37,8.27 139.69,8.59 139.56,8.59 138.71,8.16 138.56,8.14 138.3,8.14 137.7,8.74 138.3,9.34 138.56,9.34 138.71,9.33 138.84,9.27 139.45,8.95 139.58,8.95 140.37,9.33 140.5,9.35 140.8,9.35 140.93,9.33 141.71,8.93 141.75,8.91 142.06,8.6 142.12,8.6 142.33,8.64 142.38,8.65 142.51,8.65 142.56,8.64 142.92,8.56 142.96,8.53 143.46,8.03 143.71,8.03 144.02,8.07 145.1,8.07 145.14,8.07 145.42,8.03 145.57,8.03 145.63,8.01 145.7,7.96 146.03,7.79 146.06,7.77 146.08,7.74 146.1,7.61 145.99,7.52 145.97,7.51 145.94,7.51 145.94,7.49 145.82,7.35 145.66,7.42 145.56,7.61 145.49,7.67 144.02,7.67 143.99,7.68 143.71,7.72 143.46,7.72 143.11,7.37 143.07,7.34 143.03,7.33 142.71,7.26 142.66,7.25
PN on BOTTOM: 142.4,12.75 142.18,12.97 142.4,13.2 143.4,13.2 143.45,13.19 143.5,13.2 145.5,13.2 145.55,13.19 145.65,13.19 145.98,13.12 146.13,13.12 146.24,13.23 146.35,13.61 146.35,13.8 146.36,13.85 146.39,13.9 146.64,14.15 146.58,14.41 146.57,14.46 146.57,14.62 146.8,14.85 147.03,14.62 147.03,14.46 147.02,14.41 146.93,14.02 146.91,13.99 146.65,13.73 146.65,13.61 146.72,13.37 146.83,13.34 146.9,13.34 147.37,13.52 147.39,13.53 147.42,13.54 147.53,13.49 147.57,13.39 147.57,13.36 147.56,13.33 147.6,13.3 147.63,13.26 147.65,13.22 147.65,13.19 147.64,13.13 147.61,13.08 147.57,13.04 147.57,13.03 147.53,12.89 147.39,12.85 147.37,12.86 147,13 146.96,13 146.78,12.95 146.7,12.87 146.66,12.84 146.6,12.82 145.98,12.82 145.65,12.76 145.55,12.76 145.5,12.75 143.5,12.75 143.45,12.76 143.4,12.75
PN on BOTTOM: 141.35,2.85 141.02,2.92 140.78,2.92 140.72,2.94 140.67,2.97 140.62,3.02 140.27,3.21 140.2,3.38 140.34,3.49 140.36,3.49 140.36,3.51 140.47,3.65 140.64,3.58 140.83,3.23 140.84,3.23 141.02,3.23 141.35,3.3 141.42,3.3 141.79,3.3 141.84,3.36 141.86,3.37 141.91,3.42 141.95,3.45 142.01,3.46 142.19,3.46 142.35,3.62 142.35,3.81 142.28,4.11 142.28,4.16 142.28,4.33 142.5,4.55 142.72,4.33 142.72,4.16 142.72,4.11 142.65,3.81 142.65,3.79 142.78,3.52 142.79,3.48 142.8,3.42 142.8,3.25 142.73,3.09 142.57,3.02 142.4,3.02 142.35,3.03 142.15,3.07 141.98,3.07 141.88,2.97 141.83,2.94 141.78,2.92 141.45,2.85
PN on BOTTOM: 175.36,21.65 175.27,21.69 175,21.95 174.94,22.03 174.93,22.12 174.93,26.9 175.18,27.15 175.43,26.9 175.43,26.66 175.77,26.32 176.05,26.14 176.14,25.89 175.93,25.73 175.8,25.74 175.43,25.36 175.43,22.94 175.76,22.61 175.76,22.39 175.54,22.39 175.43,22.51 175.43,22.23 175.58,22.08 175.63,21.8 175.4,21.65
PN on CONDUCTIVE2: outline of 259 points within 82.25,1.55 221.87,132.95 ; 79 cut-outs
PN on CONDUCTIVE5: outline of 279 points within 82.25,1.55 221.9,132.95 ; 70 cut-outs
SIG1 on BOTTOM: 61.02,15.24 60.62,15.22 60.53,15.24 60.45,15.29 60.12,15.62 60.05,15.8 60.12,15.97 60.22,16.07 60.22,17.59 60.47,17.84 60.72,17.59 60.72,16.3 60.78,16.24 61.1,16.07 61.42,16.24 61.48,16.3 61.48,17.59 61.73,17.84 61.98,17.59 61.98,16.07 62.1,15.96 62.15,15.88 62.17,15.78 62.17,15.73 62.15,15.64 62.1,15.56 61.83,15.29 61.75,15.24 61.66,15.22 61.3,15.22 61.27,15.22 61.18,15.24 61.1,15.29
SIG1 on BOTTOM: 41.02,24.56 40.72,24.58 40.41,24.63 38.88,25.77 38.6,27.66 38.85,28.29 39.26,28.83 41,30.57 41,43.24 41.19,44.19 41.73,45.01 47,50.27 47,67.89 47.06,68.18 47.22,68.42 47.58,68.78 47.82,68.94 48.11,69 50.54,69 50.83,68.94 51.07,68.78 53.05,66.8 58.29,66.8 59.04,66.05 58.29,65.3 53.35,65.3 52,63.95 52,49.24 51.81,48.28 51.27,47.47 46,42.2 46,31.15 46.38,30.77 46.97,30.77 49.53,33.32 52.19,33.89 53.8,31.7 53.8,31.68 53.8,30.07 55.9,27.96 61.1,27.96 61.5,27.56 61.1,27.16 55.74,27.16 55.58,27.19 55.45,27.28 53.51,29.22 52.5,29.22 48.57,25.29 47.76,24.75 46.8,24.56
SIG1 on BOTTOM: 60.22,24.29 60.14,24.36 60.09,24.44 60.07,24.54 60.07,24.68 60.09,24.77 60.14,24.85 60.4,25.11 60.48,25.16 60.57,25.18 60.93,25.18 61.02,25.16 61.1,25.11 61.18,25.16 61.27,25.18 61.29,25.18 61.68,25.18 61.77,25.16 61.85,25.11 61.91,25.05 61.97,24.97 61.98,24.87 61.98,24.78 62.04,24.73 62.09,24.65 62.11,24.55 62.11,24.52 62.09,24.42 62.04,24.34 61.98,24.29 61.98,22.81 61.73,22.56 61.48,22.81 61.48,24.1 61.42,24.16 61.1,24.33 60.78,24.16 60.72,24.1 60.72,22.81 60.47,22.56 60.22,22.81
SIG1 on BOTTOM: 29.34,3.95 28.59,4.7 29.34,5.45 33.35,5.45 35.28,7.37 35.28,8.48 34.2,9.56 32.64,9.56 31.69,9.75 30.88,10.29 27.58,13.59 27.03,14.4 26.84,15.36 26.84,31.22 26.5,31.57 24.93,31.57 23.98,31.76 23.17,32.3 17.93,37.53 17.93,41.07 21.47,41.07 21.47,41.07 25.97,36.57 28.23,36.56 28.36,36.56 28.48,36.55 30.57,36.55 30.69,36.55 30.8,36.54 34.75,36.54 35.03,36.49 35.58,36.02 35.74,35.78 35.8,35.49 35.8,33.21 35.74,32.92 35.58,32.68 35.02,32.12 34.78,31.96 34.49,31.9 32.59,31.9 31.84,31.15 31.84,16.39 33.68,14.56 41.02,14.56 41.98,14.37 42.79,13.82 45.91,10.7 51.1,10.7 51.15,10.7 53.03,10.7 55.37,13.03 55.5,13.12 55.65,13.15 61.1,13.15 61.5,12.75 61.1,12.35 55.82,12.35 53.6,10.13 53.6,8.2 52.87,6.43 51.1,5.7 44.88,5.7 43.92,5.89 43.11,6.43 41.1,8.44 40.09,8.44 37.61,7.58 34.19,4.17 33.95,4.01 33.66,3.95
SIG6 on BOTTOM (solid shape): 76.22,126.18 76.68,126.12 76.9,125.71 76.8,125.43 76.57,125.24 76.51,125.22 76.51,125.08 76.57,125.06 76.87,124.42 76.22,124.12 74.67,124.68 74.34,125.15 74.67,125.62
SIG6 on TOP: 72.06,92.48 72,92.5 71.96,92.53 67.57,96.91 67.03,97.72 66.84,98.68 66.84,117.89 67.03,118.85 67.57,119.66 74.83,126.92 76.6,127.65 78.37,126.92 78.37,126.92 82.79,122.5 112.4,122.5 113.36,122.31 114.17,121.77 119.67,116.27 120.21,115.46 120.4,114.5 120.4,101.46 120.39,101.4 120.36,101.36 119.04,100.04 119,100.01 118.94,100 116.56,100 116.5,100.01 116.46,100.04 115.44,101.06 115.41,101.1 115.4,101.16 115.4,113.46 111.36,117.5 81.75,117.5 80.79,117.69 79.98,118.23 76.92,121.3 76.28,121.3 71.84,116.86 71.84,99.71 72.79,98.77 77.37,98.77 77.43,98.75 77.48,98.72 78.46,97.74 78.49,97.7 78.5,97.64 78.5,94.05 78.49,93.99 78.46,93.94 77.04,92.53 77,92.5 76.94,92.48
SIG6 on TOP: 120.69,121.8 120.54,121.82 120.41,121.87 119.69,122.25 118.28,122.25 118.22,122.26 118.17,122.29 114.66,125.81 111.19,129.28 109.52,129.28 109.42,129.32 109.37,129.43 109.37,129.77 109.37,129.78 109.34,129.95 109.51,130.03 110.13,129.9 110.78,130.55 110.65,131.17 110.65,131.2 110.73,131.34 110.88,131.33 110.91,131.31 110.93,131.28 110.94,131.23 111.27,129.62 114.87,126.02 118.34,122.55 119.69,122.55 120.41,122.93 120.54,122.98 120.69,123 121.01,123 121.61,122.4 121.01,121.8
SIG6 on TOP: 160.54,61.05 160.48,61.06 160.44,61.09 159.95,61.58 159.92,61.62 159.91,61.68 159.91,63.83 159.92,63.89 159.95,63.93 160.23,64.21 160.27,64.24 160.33,64.25 162.31,64.25 162.37,64.24 162.41,64.21 162.67,63.95 162.7,63.91 162.71,63.85 162.71,61.63 162.7,61.57 162.67,61.53 162.23,61.09 162.19,61.06 162.13,61.05
SIG6 on TOP: 116.47,11.57 110.27,17.77 110.11,18.01 110.05,18.3 110.05,28.59 108.92,29.72 107.27,29.72 107.22,29.72 107.17,29.72 105.62,30.55 105,32.2 105,41.9 104.15,42.75 94.65,42.75 93.69,42.94 92.88,43.48 89.49,46.87 88.95,47.69 88.76,48.64 90.3,50.95 93.02,50.41 95.68,47.75 97.38,47.75 98.01,48.38 98.01,48.88 97.53,49.37 96.8,51.13 97.53,52.9 99.3,53.63 101.07,52.9 109.27,44.7 109.81,43.89 110,42.93 110,30.76 111.33,29.43 111.49,29.19 111.55,28.9 111.55,18.61 117.75,12.41 117.91,12.17 117.97,11.88 117.97,10.93 117.22,10.18 116.47,10.93
SIG6 on TOP: 129.34,61.05 129.28,61.06 129.24,61.09 128.75,61.58 128.72,61.62 128.71,61.68 128.71,63.83 128.72,63.89 128.75,63.93 129.03,64.21 129.07,64.24 129.13,64.25 131.11,64.25 131.17,64.24 131.21,64.21 131.47,63.95 131.5,63.91 131.51,63.85 131.51,61.63 131.5,61.57 131.47,61.53 131.03,61.09 130.99,61.06 130.93,61.05
SIG6 on BOTTOM: outline of 89 points within 133.07,60.84 162.8,104.1
SIG6 on BOTTOM: 80.43,58.47 79.82,58.6 79.26,58.88 79.06,59.03 78.88,59.19 75.07,63 74.53,63.81 74.33,64.77 74.33,73.44 67.57,80.2 67.03,81.01 66.84,81.97 66.84,100.84 67.03,101.79 67.57,102.6 71.62,106.65 71.79,106.76 71.98,106.8 76.62,106.8 76.71,106.79 76.8,106.77 94.13,106.77 106.8,119.44 106.8,129.2 109.3,131.7 111.8,129.2 111.8,118.4 111.61,117.44 111.07,116.63 95.17,100.73 94.36,100.19 93.4,100 88.01,100 87.82,100.04 87.65,100.15 86.29,101.51 76.7,101.51 76.6,101.51 73.55,101.51 71.84,99.8 71.84,83 77.27,77.57 77.45,77.53 77.63,77.48 78.86,76.57 79.33,75.11 79.33,65.8 81.68,63.46 88.39,63.46 89.34,63.27 90.16,62.73 93.32,59.56 93.47,59.4 93.6,59.22 98.28,59.22 98.47,59.18 98.63,59.08 99.81,57.9 99.92,57.74 99.96,57.55 99.97,56.88 99.93,56.68 99.82,56.52 98.78,55.49 98.62,55.38 98.43,55.35 92.06,55.35 90.84,55.4 89.79,56.03 87.35,58.46 85.75,58.46 85.43,58.14 85.43,52.97 82.93,50.47 80.43,52.97
SIG6 on BOTTOM: 105.7,6.4 105.51,6.44 105.35,6.55 104.85,7.05 104.74,7.21 104.7,7.4 104.7,14.5 104.74,14.69 104.85,14.85 114.4,24.4 114.4,39.67 104.23,49.84 103.97,50.14 103.76,50.49 103.57,51.03 103.5,51.61 103.5,58.39 99.96,61.93 99.7,62.24 99.49,62.58 99.29,63.13 99.23,63.7 99.23,71.68 93.48,77.43 93.22,77.73 93.01,78.08 92.82,78.62 92.75,79.19 92.75,86.72 89.39,90.08 80.26,90.08 80.11,90.09 79.96,90.1 77.5,90.1 77.31,90.14 77.15,90.25 75.85,91.55 75.74,91.71 75.7,91.9 75.7,98.26 75.85,98.61 76.2,98.76 77.34,98.76 77.53,98.72 77.7,98.61 79.79,96.51 80,96.36 80.19,96.19 81.3,95.08 90.42,95.08 91.38,94.89 92.19,94.35 97.02,89.52 97.56,88.71 97.75,87.76 97.75,80.23 103.49,74.48 104.04,73.67 104.23,72.72 104.23,64.74 107.77,61.2 108.31,60.39 108.5,59.43 108.5,52.64 118.67,42.47 119.21,41.66 119.4,40.71 119.4,23.37 119.21,22.41 118.67,21.6 113.3,16.23 113.3,9.51 113.26,9.32 113.15,9.15 110.55,6.55 110.38,6.44 110.19,6.4
SIG6 on BOTTOM: 129.34,61.05 129.28,61.06 129.24,61.09 128.75,61.58 128.72,61.62 128.71,61.68 128.71,62.09 127.15,63.65 126.93,63.78 126.74,63.94 125.14,65.54 124.81,66.03 124.7,66.6 124.7,70.93 120.24,75.39 120.2,75.43 120.16,75.47 117.76,75.47 117.7,75.49 117.66,75.52 116.79,76.39 116.74,76.45 116.7,76.6 116.7,79.66 111.51,84.86 110.97,85.67 110.78,86.62 110.78,94.54 108.43,96.88 108.17,97.19 107.96,97.53 107.77,98.08 107.7,98.65 107.7,102.5 110.2,105 112.7,102.5 112.7,99.69 115.04,97.34 115.45,96.81 115.7,96.18 115.76,95.88 115.78,95.58 115.78,87.66 120.97,82.47 121.43,81.82 121.67,81.06 121.69,80.98 121.7,80.9 121.7,78.27 121.74,78.12 121.79,78.06 122.2,77.65 122.28,77.58 122.36,77.51 127.26,72.61 127.59,72.12 127.7,71.55 127.7,67.22 128.86,66.06 128.96,65.95 129.05,65.82 130.63,64.25 131.11,64.25 131.17,64.24 131.21,64.21 131.47,63.95 131.5,63.91 131.51,63.85 131.51,61.63 131.5,61.57 131.47,61.53 131.03,61.09 130.99,61.06 130.93,61.05
SIG15 on BOTTOM: 133.65,77.14 133.63,77.17 133.62,77.22 133.4,78.39 129.16,82.63 129.1,82.63 128.89,82.58 128.82,82.58 128.63,82.69 128.63,82.91 128.63,82.92 128.6,83.01 128.64,83.11 128.85,83.31 128.85,83.84 128.74,84.19 128.73,84.24 128.72,84.28 128.72,84.88 129,85.15 129.28,84.88 129.28,84.28 129.27,84.24 129.26,84.19 129.15,83.84 129.15,83.06 129.31,82.9 133.61,78.6 134.78,78.38 134.83,78.37 134.86,78.35 134.88,78.32 134.89,78.18 134.79,78.09 134.76,78.09 134.73,78.09 134.2,78.19 133.81,77.8 133.91,77.27 133.91,77.24 133.91,77.21 133.82,77.11 133.68,77.12
SIG18 on TOP: 147.5,60.89 147.44,60.9 147.4,60.93 146.91,61.42 146.88,61.46 146.87,61.52 146.87,63.67 146.88,63.73 146.91,63.77 147.19,64.05 147.23,64.08 147.29,64.09 149.27,64.09 149.33,64.08 149.37,64.05 149.63,63.79 149.66,63.75 149.67,63.69 149.67,61.47 149.66,61.41 149.63,61.37 149.19,60.93 149.15,60.9 149.09,60.89
SIG20 on BOTTOM: 110.26,77.93 110.28,77.97 110.95,78.95 110.95,81.74 110.04,82.65 108.38,82.65 108.05,82.58 108,82.58 107.83,82.58 107.62,82.7 107.65,82.94 107.64,82.94 107.6,83.05 107.64,83.16 107.85,83.36 107.85,85.34 107.74,85.69 107.73,85.74 107.72,85.78 107.72,86.38 108,86.65 108.28,86.38 108.28,85.78 108.27,85.74 108.26,85.69 108.15,85.34 108.15,83.36 108.56,82.95 110.1,82.95 110.16,82.94 111.24,81.86 111.25,81.8 111.25,78.95 111.92,77.97 111.94,77.93 111.95,77.88 111.89,77.76 111.75,77.74 111.72,77.75 111.68,77.8 111.38,78.24 110.82,78.24 110.52,77.8 110.48,77.75 110.45,77.74 110.31,77.76 110.25,77.88
SIG22 on TOP: 116.3,60.89 116.24,60.9 116.2,60.93 115.71,61.42 115.68,61.46 115.67,61.52 115.67,63.67 115.68,63.73 115.71,63.77 115.99,64.05 116.03,64.08 116.09,64.09 118.07,64.09 118.13,64.08 118.17,64.05 118.43,63.79 118.46,63.75 118.47,63.69 118.47,61.47 118.46,61.41 118.43,61.37 117.99,60.93 117.95,60.9 117.89,60.89
SIG22 on BOTTOM: 115.84,60.8 115.73,60.84 115.69,60.95 115.69,61.45 115.67,61.49 115.67,61.52 115.67,63.67 115.67,63.7 115.69,63.74 115.69,66.23 115.7,66.28 115.73,66.33 117.2,67.8 117.2,71.97 117.24,72.08 117.35,72.12 119.91,72.12 119.96,72.11 120.01,72.08 121.36,70.74 121.39,70.69 121.4,70.63 121.4,67.31 121.39,67.25 121.36,67.2 120.31,66.16 120.29,66.14 119.6,65.58 119.06,64.9 118.69,64.17 118.47,63.38 118.47,61.47 118.46,61.41 118.43,61.37 118.41,61.35 118.41,60.95 118.37,60.84 118.26,60.8
SIG23 on TOP: 157.8,45.45 156.75,46.5 157.8,47.55 159.05,47.55 159.37,47.5 159.65,47.36 160.67,46.65 160.72,46.65 162.45,48.38 162.45,54.59 161.81,55.23 161.52,55.23 160.89,54.87 160.31,54.87 160.01,55.38 160.01,55.67 160.04,55.85 160.13,56.02 160.28,56.22 160.28,56.51 160.04,56.75 155.95,56.75 155.89,56.76 155.84,56.79 153.59,59.04 153.56,59.09 153.55,59.15 153.55,60.59 153.36,60.89 152.94,60.89 152.88,60.9 152.84,60.93 152.35,61.42 152.32,61.46 152.31,61.52 152.31,63.67 152.32,63.73 152.35,63.77 152.63,64.05 152.67,64.08 152.73,64.09 154.71,64.09 154.77,64.08 154.81,64.05 155.07,63.79 155.1,63.75 155.11,63.69 155.11,61.47 155.1,61.41 155.07,61.37 154.63,60.93 154.59,60.9 154.53,60.89 154.04,60.89 153.85,60.59 153.85,59.21 156.01,57.05 160.1,57.05 160.16,57.04 160.71,56.51 160.72,56.49 161.15,55.87 161.18,55.72 161.52,55.52 161.88,55.52 161.93,55.51 162.74,54.71 162.75,54.65 162.75,48.32 162.74,48.26 160.88,46.39 160.84,46.36 160.78,46.35 160.67,46.35 159.65,45.64 159.37,45.5 159.05,45.45
SIG23 on TOP: 157.64,50.82 157.6,50.84 157.55,50.89 157.53,50.96 157.55,51.02 157.58,51.07 157.6,51.09 157.88,51.27 158.19,51.58 158.19,53.19 158.21,53.32 158.26,53.44 158.4,53.65 158.4,53.93 158.2,54.35 158.19,54.46 158.19,55.1 158.65,55.56 159.11,55.1 159.11,54.46 159.1,54.35 159.06,54.25 158.9,53.93 158.9,53.65 159.04,53.44 159.09,53.33 159.11,53.21 159.43,53.05 159.72,53.05 160.17,53.32 160.31,53.39 160.47,53.41 160.6,53.41 161.19,52.83 160.6,52.24 160.47,52.24 160.33,52.26 160.2,52.31 159.74,52.55 159.43,52.55 159.11,52.39 159.11,52.13 159.1,52.08 159.07,52.03 158.1,51.06 157.91,50.78 157.89,50.75 157.77,50.71 157.66,50.78
SIG23 on TOP: 153.35,54.55 152.8,55.1 153.35,55.65 154,55.65 154.12,55.63 154.72,55.35 155.13,55.35 155.59,55.55 155.68,55.56 155.95,55.56 156.41,55.1 155.95,54.64 155.68,54.64 155.59,54.65 155.13,54.85 154.72,54.85 154.12,54.57 154,54.55
SIG23 on BOTTOM: 152.94,60.89 152.88,60.9 152.84,60.93 152.35,61.42 152.32,61.46 152.31,61.52 152.31,63.67 152.32,63.73 152.35,63.77 152.63,64.05 152.67,64.08 152.73,64.09 154.71,64.09 154.77,64.08 154.81,64.05 155.07,63.79 155.1,63.75 155.11,63.69 155.11,61.47 155.1,61.41 155.07,61.37 154.63,60.93 154.59,60.9 154.53,60.89
SIG24 on TOP: 152.28,49 152.28,49.05 152.35,49.38 152.35,49.7 152.07,49.98 152.04,50.03 152.03,50.09 152.03,50.24 151.91,50.62 151.9,50.66 151.9,50.7 151.9,50.89 151.9,50.93 151.91,50.98 152.03,51.33 152.03,51.4 152.04,51.46 152.28,51.71 152.28,51.94 152.1,52.25 152.05,52.25 151.7,52.38 151.51,52.7 151.4,53.29 151.37,53.32 151.34,53.37 151.32,53.42 151.32,54.27 151.12,54.72 151.05,54.75 150.99,54.79 150.61,55.11 145.63,55.11 145.16,54.88 145.07,54.86 144.98,54.84 144.74,54.84 144.33,55.26 144.74,55.67 144.98,55.67 145.07,55.66 145.16,55.63 145.63,55.41 150.65,55.41 151.24,55.5 151.47,55.5 151.76,55.38 151.88,55.1 151.88,54.9 151.87,54.81 151.84,54.73 151.62,54.27 151.62,53.5 152.13,53.35 152.43,53.35 152.9,53.08 152.91,52.54 152.57,51.94 152.57,51.65 152.56,51.59 152.36,51.38 152.36,51.2 152.44,50.98 152.45,50.93 152.45,50.89 152.45,50.7 152.45,50.66 152.32,50.24 152.32,50.15 152.64,49.82 152.65,49.76 152.65,49.38 152.72,49.05 152.72,49 152.72,48.83 152.5,48.6 152.28,48.83
SIG25 on TOP: outline of 88 points within 130.2,52.86 142.34,55.75
SIG25 on TOP: 133.3,50.09 133.3,50.13 133.31,50.18 133.43,50.53 133.43,50.6 133.44,50.66 133.88,51.11 133.88,51.13 133.81,51.44 133.8,51.49 133.8,51.6 133.87,51.76 134.03,51.83 134.2,51.83 134.25,51.82 134.58,51.75 134.82,51.75 135.22,52.15 135.22,52.16 134.99,52.39 134.96,52.44 134.95,52.5 134.95,52.77 134.88,53.1 134.88,53.17 135.1,53.4 135.32,53.17 135.32,53.1 135.25,52.77 135.25,52.56 135.51,52.28 135.53,52.23 135.53,52.15 135.59,51.83 135.6,51.78 135.6,51.6 135.53,51.44 135.38,51.38 135.2,51.38 135.15,51.38 134.82,51.45 134.58,51.45 134.25,51.38 134.23,51.38 134.18,51.13 134.18,51.05 134.16,50.99 133.72,50.54 133.72,50.53 133.84,50.18 133.85,50.13 133.85,50.09 133.85,49.9 133.57,49.62 133.3,49.9
SIG27 on TOP: 129.03,52.35 128.89,52.37 128.34,52.65 127.93,52.65 127.61,52.49 127.51,52.45 127.4,52.44 127.15,52.44 126.69,52.9 127.15,53.36 127.4,53.36 127.51,53.35 127.61,53.31 127.93,53.15 128.34,53.15 128.89,53.43 129.03,53.45 129.62,53.45 130.18,52.9 129.62,52.35
SIG27 on TOP: 122.5,52.24 121.92,52.83 122.5,53.41 122.75,53.41 122.88,53.4 123,53.36 123.6,53.08 123.64,53.08 123.99,53.25 123.99,53.29 124.01,53.42 124.06,53.54 124.2,53.75 124.2,54.03 124,54.45 123.99,54.56 123.99,55.7 124.03,55.9 124.16,56.06 124.3,56.36 124.3,56.71 124.31,56.77 124.34,56.82 124.73,57.21 124.77,57.23 124.81,57.25 125.15,57.32 125.2,57.33 125.38,57.33 125.6,57.1 125.38,56.88 125.2,56.88 125.15,56.88 124.98,56.92 124.87,56.92 124.6,56.65 124.6,56.36 124.74,56.06 124.87,55.9 124.91,55.7 124.91,54.56 124.9,54.45 124.86,54.35 124.7,54.03 124.7,53.75 124.84,53.54 124.89,53.42 124.91,53.29 124.91,52.9 124.78,52.57 124.45,52.44 124.31,52.44 124.21,52.45 124.11,52.49 123.94,52.58 123.42,52.58 123.09,52.35 122.93,52.27 122.75,52.24
SIG27 on TOP: 121.74,60.89 121.68,60.9 121.64,60.93 121.15,61.42 121.12,61.46 121.11,61.52 121.11,63.67 121.12,63.73 121.15,63.77 121.43,64.05 121.47,64.08 121.53,64.09 121.87,64.09 122.35,64.57 122.35,68.4 122.36,68.46 122.75,68.86 122.97,70.09 123.33,70.71 124,70.95 124.8,70.95 125.85,69.9 124.8,68.85 124.09,68.85 122.96,68.65 122.65,68.34 122.65,64.57 123.13,64.09 123.51,64.09 123.57,64.08 123.61,64.05 123.87,63.79 123.9,63.75 123.91,63.69 123.91,61.47 123.9,61.41 123.87,61.37 123.43,60.93 123.39,60.9 123.33,60.89
SIG27 on BOTTOM: 121.74,60.89 121.68,60.9 121.64,60.93 121.15,61.42 121.12,61.46 121.11,61.52 121.11,63.67 121.12,63.73 121.15,63.77 121.43,64.05 121.47,64.08 121.53,64.09 123.51,64.09 123.57,64.08 123.61,64.05 123.87,63.79 123.9,63.75 123.91,63.69 123.91,61.47 123.9,61.41 123.87,61.37 123.43,60.93 123.39,60.9 123.33,60.89
SIG43 on BOTTOM: 146.03,3.02 145.87,3.09 145.8,3.25 145.8,3.42 145.81,3.48 145.88,3.78 145.88,3.99 145.64,4.23 145.03,4.23 145,4.22 144.57,4.22 144.28,4.53 144.57,4.83 145,4.83 145.06,4.82 145.11,4.81 145.48,4.67 145.55,4.67 145.61,4.66 146.16,4.11 146.18,4.05 146.18,3.78 146.46,3.42 146.57,3.42 146.87,3.49 146.93,3.5 147.1,3.5 147.32,3.27 147.1,3.05 146.93,3.05 146.87,3.06 146.68,3.1 146.58,3.1 146.25,3.03 146.2,3.02
SIG45 on BOTTOM: 143.2,3.42 143.21,3.48 143.28,3.78 143.28,4.97 143.29,5.03 143.62,5.38 143.67,5.41 143.72,5.42 144.03,5.47 144.57,5.47 144.78,5.28 144.57,5.08 143.74,5.08 143.57,4.91 143.57,3.78 143.64,3.48 143.65,3.42 143.65,2.15 143.43,1.93 143.2,2.15
SIG47 on BOTTOM: 149.85,8.97 149.81,8.98 149.53,9.03 149.3,9.03 149.24,9.04 149.19,9.07 147.39,10.87 147.36,10.92 147.35,10.98 147.35,11.12 147.15,11.62 147.14,11.69 147.14,11.91 147.5,12.27 147.86,11.91 147.86,11.69 147.85,11.62 147.65,11.12 147.65,11.04 149.36,9.32 149.53,9.32 149.81,9.37 149.85,9.38 150.43,9.38 150.62,9.18 150.43,8.97
SIG0052 on BOTTOM: 237.07,107.74 236.69,107.85 234.9,107.85 234.84,107.86 234.79,107.89 234.07,108.62 233.82,108.54 233.79,108.53 233.77,108.53 233.67,108.56 233.62,108.64 233.62,108.64 233.47,108.64 233.32,108.8 233.47,108.94 233.62,108.94 233.62,108.95 233.67,109.03 233.77,109.06 233.79,109.06 233.82,109.05 234.15,108.94 234.18,108.92 234.21,108.9 234.96,108.15 236.69,108.15 237.07,108.26 237.13,108.27 237.18,108.25 237.25,108.18 237.26,108.08 237.24,108.04 237.2,108 237.22,107.99 237.24,107.96 237.26,107.93 237.24,107.79 237.11,107.73
SIG52 on BOTTOM: 143.43,9.68 143.37,9.69 143.32,9.72 142.17,10.86 142.14,10.91 142.13,10.97 142.13,11.57 142.06,11.9 142.06,11.95 142.06,12.12 142.14,12.3 142.37,12.35 142.4,12.35 143.4,12.35 143.62,12.12 143.4,11.9 142.61,11.9 142.43,11.72 142.43,11.03 143.49,9.97 144.57,9.97 144.72,9.82 144.57,9.68
